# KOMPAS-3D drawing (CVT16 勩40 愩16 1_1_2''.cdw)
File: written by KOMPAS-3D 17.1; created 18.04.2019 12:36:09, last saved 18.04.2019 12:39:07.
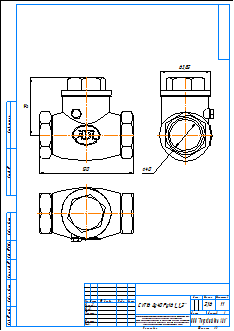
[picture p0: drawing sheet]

Sheet 1: A3, portrait

Title block, sheet 1: name: CVT16 Ду40 Ру16 1_1_2''; material: Внимание! Данный продукт является объектом авторского права ООО «Торговый Дом АДЛ». / Запрещается изменение, копирование, распространение / (в том числе путем копирования на другие сайты и ресурсы в Интернете) / или любое иное использование информации и объектов без предварительного / согласия правообладателя (ООО «Торговый Дом АДЛ»).; mass: 2,16; sheets: 1; organisation: ООО "Торговый дом АДЛ"; sheet format: A3

Views: Вид 1, Проекционный вид 2, Проекционный вид 3
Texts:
  user
Dimensions and other numbers on the sheet: 120; 73; 63,82; 40; 1:1; 1; 2,16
